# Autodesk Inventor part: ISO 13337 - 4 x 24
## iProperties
Created: 2001-08
Part Number: ISO 13337 - 4 x 24
Catalog Web Link: file:///D:/Program%20Files/Autodesk/Inventor%205/Content/Iso/index.htm?doNavigateId=BE0D2556-A8D8-4073-8A7F-C202F694A8F6|1F7F92DCFD174A5EB45CB16CB903DB04|true
Description: Spring-Type Straight Pin
Document SubType Name: Standard Catalog Part
Standard: ISO 13337 - 4 x 24
Designer: Martin Budgell
Control State: 0
Master: False
Checked Out: False
Length Units: 11269
Angle Units: 11279
Time Units: 11290
Mass Units: 11283
Shininess: 3
Angle Display Precision: 2
Document Length Units: 11269
Document Angle Units: 11279
Document Time Units: 11290
Document Mass Units: 11283
Document Length Units Precision: 3
Document Angle Units Precision: 2
Compacted: True
CLASSIFICATION: 31163201 un/spsc
MANUFACTURER: ISO Standard System
Density: 0.0
Volumn: 0.0
Area: 0.0
PropertySet Name: Model Information
Author: Martin Budgell
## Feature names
1. Base1
